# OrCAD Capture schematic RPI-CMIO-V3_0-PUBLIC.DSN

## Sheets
1 PAGE1 - CONTENTS: title: Raspberry Pi Compute Module IO Board; rev: 3.0; company: Raspberry Pi; note: RPI-CMIO
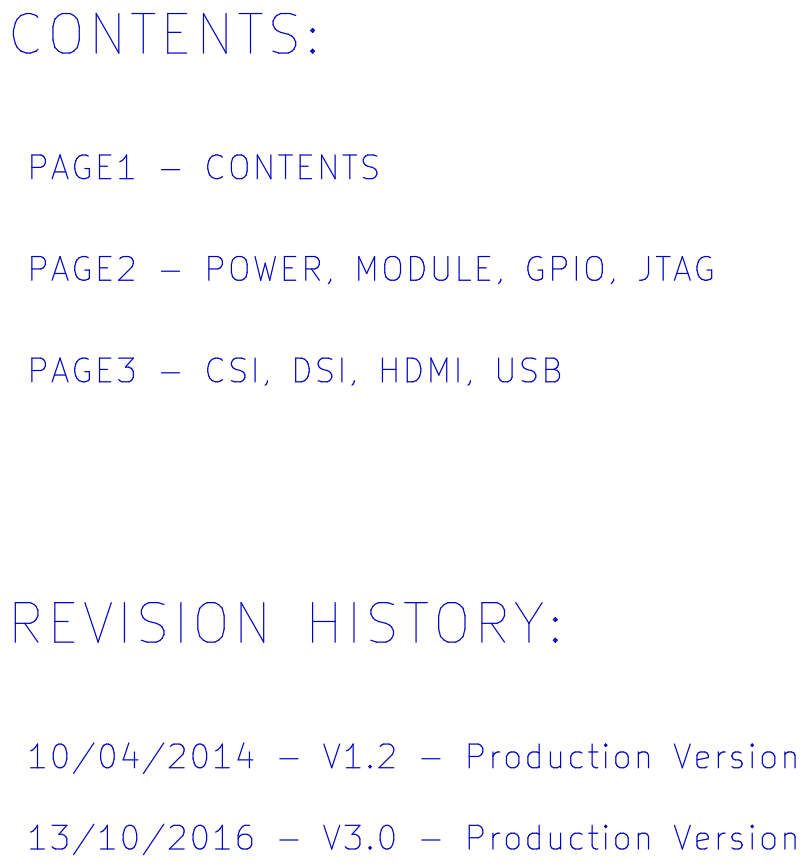
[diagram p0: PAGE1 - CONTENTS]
2 PAGE2 - PWR, CM, GPIO, JTAG: size A2
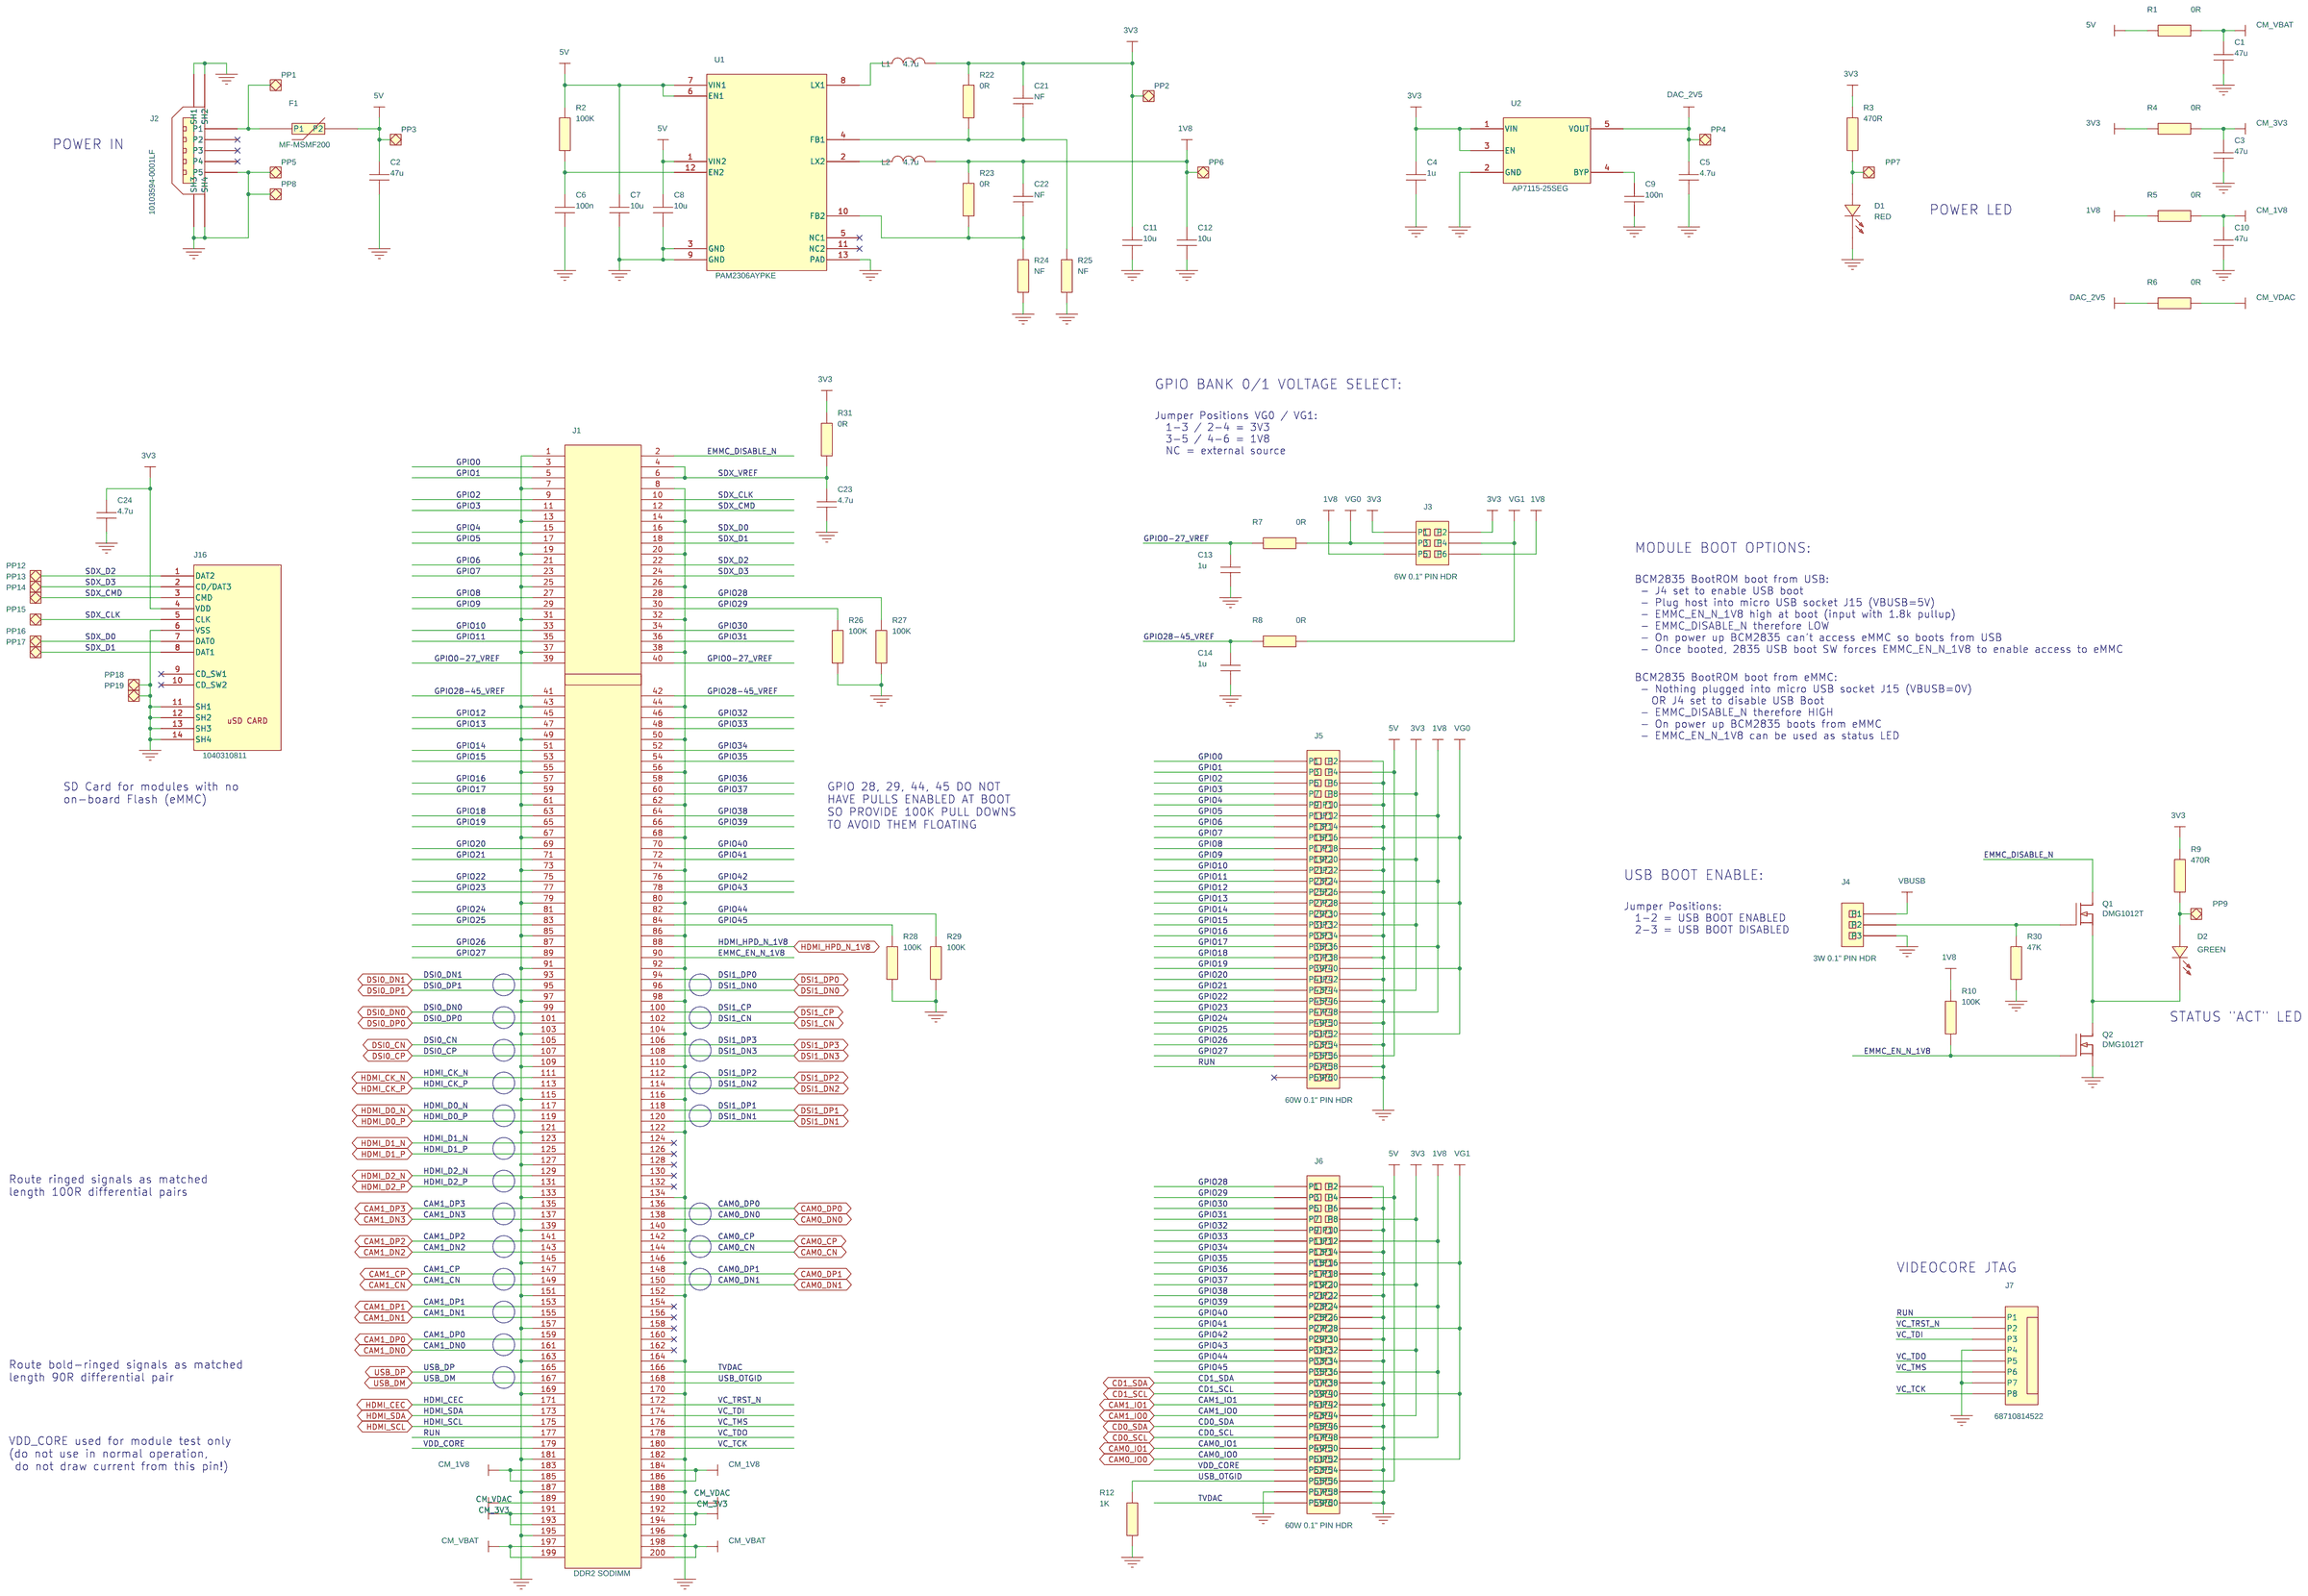
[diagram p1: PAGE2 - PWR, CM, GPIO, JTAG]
3 PAGE3 - CSI, DSI, HDMI, USB: size A2
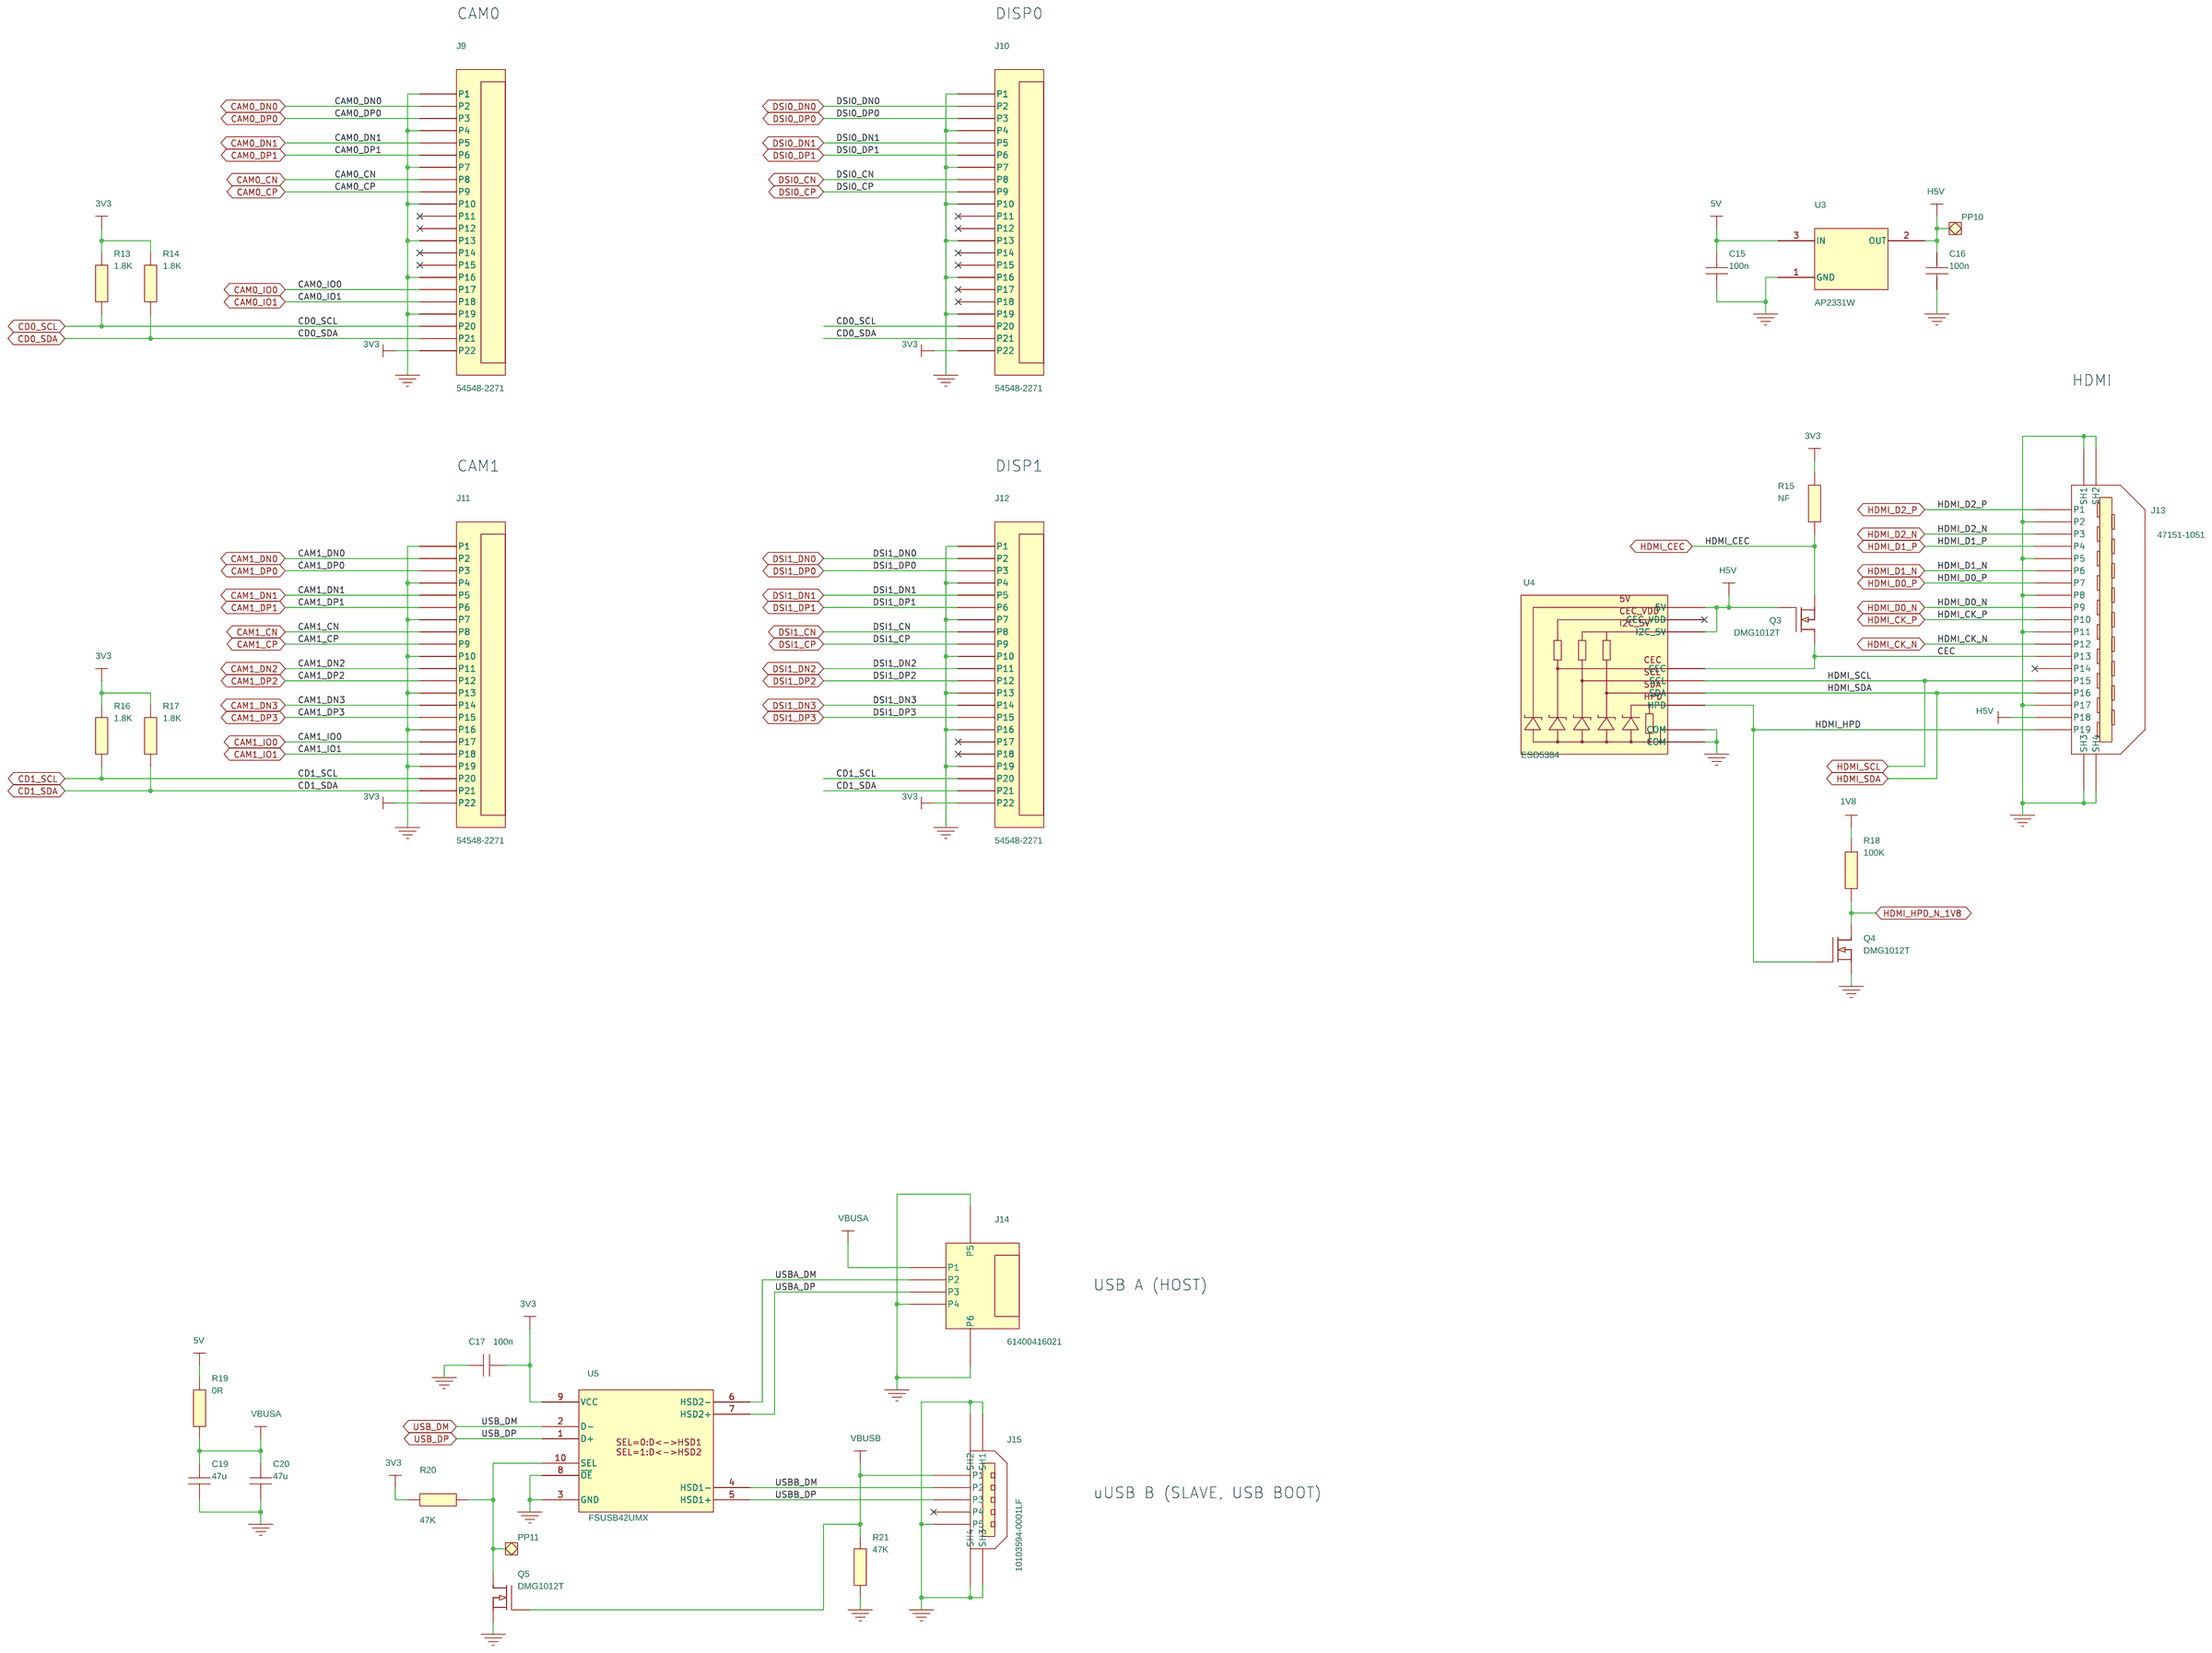
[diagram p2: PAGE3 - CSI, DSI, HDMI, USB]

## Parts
sheet PAGE2 - PWR, CM, GPIO, JTAG
C1  47u  [CAPC3216X180N]
C2  47u  [CAPC3216X180N]
C3  47u  [CAPC3216X180N]
C4  1u  [CAPC1005X55N]
C5  4.7u  [CAPC1608X90N]
C6  100n  [CAPC1005X55N]
C7  10u  [CAPC2012X145N]
C8  10u  [CAPC2012X145N]
C9  100n  [CAPC1005X55N]
C10  47u  [CAPC3216X180N]
C11  10u  [CAPC2012X145N]
C12  10u  [CAPC2012X145N]
C13  1u  [CAPC1005X55N]
C14  1u  [CAPC1005X55N]
C21  NF  [CAPC1005X55N]
C22  NF  [CAPC1005X55N]
C23  4.7u  [CAPC1608X90N]
C24  4.7u  [CAPC1608X90N]
D1  RED  [LEDC1608X80N]
D2  GREEN  [LEDC1608X80N]
F1  MF-MSMF200  [BOURNS_MF-MSMF150]
J1  DDR2 SODIMM  [FCI_10033853_CM]
J2  10103594-0001LF  [FCI_10103594-0001LF]
J3  6W 0.1" PIN HDR  [PINHDR_6W_2P54MM]
J4  3W 0.1" PIN HDR  [PINHDR_3W_2P54MM]
J5  60W 0.1" PIN HDR  [PINHDR_60W_2P54MM]
J6  60W 0.1" PIN HDR  [PINHDR_60W_2P54MM]
J7  68710814522  [WE_68710814522]
J16  1040310811  [MOLEX_1040310811]
L1  4.7u  [BOURNS_SRN4018]
L2  4.7u  [BOURNS_SRN4018]
PP1  PP_SMT_ROUND_2MM  [PP_SMT_R2MM]
PP2  PP_SMT_ROUND_2MM  [PP_SMT_R2MM]
PP3  PP_SMT_ROUND_2MM  [PP_SMT_R2MM]
PP4  PP_SMT_ROUND_2MM  [PP_SMT_R2MM]
PP5  PP_SMT_ROUND_2MM  [PP_SMT_R2MM]
PP6  PP_SMT_ROUND_2MM  [PP_SMT_R2MM]
PP7  PP_SMT_ROUND_2MM  [PP_SMT_R2MM]
PP8  PP_SMT_ROUND_2MM  [PP_SMT_R2MM]
PP9  PP_SMT_ROUND_2MM  [PP_SMT_R2MM]
PP12  PP_SMT_ROUND_2MM  [PP_SMT_R2MM]
PP13  PP_SMT_ROUND_2MM  [PP_SMT_R2MM]
PP14  PP_SMT_ROUND_2MM  [PP_SMT_R2MM]
PP15  PP_SMT_ROUND_2MM  [PP_SMT_R2MM]
PP16  PP_SMT_ROUND_2MM  [PP_SMT_R2MM]
PP17  PP_SMT_ROUND_2MM  [PP_SMT_R2MM]
PP18  PP_SMT_ROUND_2MM  [PP_SMT_R2MM]
PP19  PP_SMT_ROUND_2MM  [PP_SMT_R2MM]
Q1  DMG1012T  [SOT50P160X90-3N]
Q2  DMG1012T  [SOT50P160X90-3N]
R1  0R  [RESC2012X65N]
R2  100K  [RESC1005X40N]
R3  470R  [RESC1005X40N]
R4  0R  [RESC2012X65N]
R5  0R  [RESC2012X65N]
R6  0R  [RESC2012X65N]
R7  0R  [RESC2012X65N]
R8  0R  [RESC2012X65N]
R9  470R  [RESC1005X40N]
R10  100K  [RESC1005X40N]
R12  1K  [RESC1005X40N]
R22  0R  [RESC1005X40N]
R23  0R  [RESC1005X40N]
R24  NF  [RESC1005X40N]
R25  NF  [RESC1005X40N]
R26  100K  [RESC1005X40N]
R27  100K  [RESC1005X40N]
R28  100K  [RESC1005X40N]
R29  100K  [RESC1005X40N]
R30  47K  [RESC1005X40N]
R31  0R  [RESC2012X65N]
U1  PAM2306AYPKE  [DIODES_PAM2306]
U2  AP7115-25SEG  [SOT65P210X100-5N]
sheet PAGE3 - CSI, DSI, HDMI, USB
C15  100n  [CAPC1005X55N]
C16  100n  [CAPC1005X55N]
C17  100n  [CAPC1005X55N]
C19  47u  [CAPC3216X180N]
C20  47u  [CAPC3216X180N]
J9  54548-2271  [MOLEX_54548-2271]
J10  54548-2271  [MOLEX_54548-2271]
J11  54548-2271  [MOLEX_54548-2271]
J12  54548-2271  [MOLEX_54548-2271]
J13  47151-1051  [MOLEX_47151-1051]
J14  61400416021  [WURTH_61400416021]
J15  10103594-0001LF  [FCI_10103594-0001LF]
PP10  PP_SMT_ROUND_2MM  [PP_SMT_R2MM]
PP11  PP_SMT_ROUND_2MM  [PP_SMT_R2MM]
Q3  DMG1012T  [SOT50P160X90-3N]
Q4  DMG1012T  [SOT50P160X90-3N]
Q5  DMG1012T  [SOT50P160X90-3N]
R13  1.8K  [RESC1005X40N]
R14  1.8K  [RESC1005X40N]
R15  NF  [RESC1005X40N]
R16  1.8K  [RESC1005X40N]
R17  1.8K  [RESC1005X40N]
R18  100K  [RESC1005X40N]
R19  0R  [RESC2012X65N]
R20  47K  [RESC1005X40N]
R21  47K  [RESC1005X40N]
U3  AP2331W  [SOT95P280X135-3N]
U4  ESD5384  [ONSEMI_ESD5384]
U5  FSUSB42UMX  [FAIRCHILD_FSUSB42UMX]

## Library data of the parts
C1-C3 C10 C19 C20 = CAP_3216_6.3V_47u
C4 C13 C14 = CAP_1005_6.3V_1u
C5 C23 C24 = CAP_1608_6.3V_4.7u
C6 C9 C15-C17 = CAP_1005_6.3V_100n
C7 C8 C11 C12 = CAP_2012_6.3V_10u
C21 C22 = CAP_1005_NF
D1 = LED_1608_RED
D2 = LED_1608_GREEN
F1 = FUSE_POLY_2.0A_6V
J1 = CON_200W_DDR2SODIMM_CM
J2 J15 = CON_uUSB_B
J3 = CON_6W_PINHDR
J4 = CON_3W_PINHDR
J5 J6 = CON_60W_PINHDR
J7 = CON_FFC_8W
J16 = CON_uSD_1040310811
L1 L2 = IND_4u7_SRN4018-4R7M
PP1-PP19 = PP_SMT_ROUND_2MM
Q1-Q5 = MOSFET_N_DMG1012T
R1 R4-R8 R19 R31 = RES_2012_0R
R2 R10 R18 R26-R29 = RES_1005_100K
R3 R9 = RES_1005_470R
R12 = RES_1005_1K
R22 R23 = RES_1005_0R
R24 R25 = RES_1005_NF
R20 R21 R30 = RES_1005_47K
U1 = IC_SMPS_DUAL_1A_3V3_1V8
U2 = IC_AP7115-25SEG
J9-J12 = CON_22W_FFC_54548-2271
J13 = CON_HDMI_RA
J14 = CON_USBA_RA_PTH
R13 R14 R16 R17 = RES_1005_1.8K
R15 = RES_1005_27K
U3 = IC_AP2331W
U4 = IC_ESD5384
U5 = IC_MUX2-1_USB

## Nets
1V8: C12.1 C22.1 J3.5(P5) J3.6(P6) J5.12(P12) J5.24(P24) J5.36(P36) J5.48(P48) J6.12(P12) J6.24(P24) J6.36(P36) J6.48(P48) L2.2 PP6.1 R5.1 R10.1 R18.1 R23.1
3V3: C4.1 C11.1 C17.2 C21.1 C24.1 J3.1(P1) J3.2(P2) J5.8(P8) J5.20(P20) J5.32(P32) J5.44(P44) J6.8(P8) J6.20(P20) J6.32(P32) J6.44(P44) J9.22(P22) J10.22(P22) J11.22(P22) J12.22(P22) J16.4(VDD) L1.2 PP2.1 R3.1 R4.1 R9.1 R13.1 R14.1 R15.2 R16.1 R17.1 R20.1 R22.1 R31.2 U2.1(VIN) U2.3(EN) U5.9(VCC)
5V: C2.1 C7.1 C8.1 C15.1 F1.2(P2) J5.4(P4) J5.56(P56) J6.4(P4) J6.56(P56) PP3.1 R1.1 R2.1 R19.1 U1.1(VIN2) U1.6(EN1) U1.7(VIN1) U3.3(IN)
GND: C1.2 C2.2 C3.2 C4.2 C5.2 C6.2 C7.2 C8.2 C9.2 C10.2 C11.2 C12.2 C13.2 C14.2 C15.2 C16.2 C17.1 C19.2 C20.2 C23.2 C24.2 D1.1(CATHODE) J1.1 J1.7 J1.8 J1.13 J1.14 J1.19 J1.20 J1.25 J1.26 J1.31 J1.32 J1.37 J1.38 J1.43 J1.44 J1.49 J1.50 J1.55 J1.56 J1.61 J1.62 J1.67 J1.68 J1.73 J1.74 J1.79 J1.80 J1.85 J1.86 J1.91 J1.92 J1.97 J1.98 J1.103 J1.104 J1.109 J1.110 J1.115 J1.116 J1.121 J1.122 J1.127 J1.133 J1.134 J1.139 J1.140 J1.145 J1.146 J1.151 J1.152 J1.157 J1.163 J1.164 J1.169 J1.170 J1.181 J1.182 J1.187 J1.188 J1.195 J1.196 J2.5(P5) J2.6(SH1) J2.7(SH2) J2.8(SH3) J2.9(SH4) J4.3(P3) J5.2(P2) J5.6(P6) J5.10(P10) J5.14(P14) J5.18(P18) J5.22(P22) J5.26(P26) J5.30(P30) J5.34(P34) J5.38(P38) J5.42(P42) J5.46(P46) J5.50(P50) J5.54(P54) J5.58(P58) J5.60(P60) J6.2(P2) J6.6(P6) J6.10(P10) J6.14(P14) J6.18(P18) J6.22(P22) J6.26(P26) J6.30(P30) J6.34(P34) J6.38(P38) J6.42(P42) J6.46(P46) J6.50(P50) J6.54(P54) J6.57(P57) J6.58(P58) J6.60(P60) J7.4(P4) J7.7(P7) J9.1(P1) J9.4(P4) J9.7(P7) J9.10(P10) J9.13(P13) J9.16(P16) J9.19(P19) J10.1(P1) J10.4(P4) J10.7(P7) J10.10(P10) J10.13(P13) J10.16(P16) J10.19(P19) J11.1(P1) J11.4(P4) J11.7(P7) J11.10(P10) J11.13(P13) J11.16(P16) J11.19(P19) J12.1(P1) J12.4(P4) J12.7(P7) J12.10(P10) J12.13(P13) J12.16(P16) J12.19(P19) J13.2(P2) J13.5(P5) J13.8(P8) J13.11(P11) J13.17(P17) J13.20(SH1) J13.21(SH2) J13.22(SH3) J13.23(SH4) J14.4(P4) J14.5(P5) J14.6(P6) J15.5(P5) J15.6(SH1) J15.7(SH2) J15.8(SH3) J15.9(SH4) J16.6(VSS) J16.11(SH1) J16.12(SH2) J16.13(SH3) J16.14(SH4) PP5.1 PP8.1 PP18.1 PP19.1 Q2.2(S) Q4.2(S) Q5.2(S) R12.1 R21.2 R24.2 R25.2 R26.2 R27.2 R28.2 R29.2 R30.2 U1.3(GND) U1.9(GND) U1.13(PAD) U2.2(GND) U3.1(GND) U4.B2(COM) U4.C2(COM) U5.3(GND) U5.8(~{OE})
VBUSA: C19.1 C20.1 J14.1(P1) R19.2
VBUSB: J4.1(P1) J15.1(P1) Q5.1(G) R21.1
VDD_CORE: J1.179 J6.53(P53)
CAM0_CN: J1.144 J9.8(P8)
CAM0_CP: J1.142 J9.9(P9)
CAM0_DN0: J1.138 J9.2(P2)
CAM0_DN1: J1.150 J9.5(P5)
CAM0_DP0: J1.136 J9.3(P3)
CAM0_DP1: J1.148 J9.6(P6)
CAM0_IO0: J6.51(P51) J9.17(P17)
CAM0_IO1: J6.49(P49) J9.18(P18)
CAM1_CN: J1.149 J11.8(P8)
CAM1_CP: J1.147 J11.9(P9)
CAM1_DN0: J1.161 J11.2(P2)
CAM1_DN1: J1.155 J11.5(P5)
CAM1_DN2: J1.143 J11.11(P11)
CAM1_DN3: J1.137 J11.14(P14)
CAM1_DP0: J1.159 J11.3(P3)
CAM1_DP1: J1.153 J11.6(P6)
CAM1_DP2: J1.141 J11.12(P12)
CAM1_DP3: J1.135 J11.15(P15)
CAM1_IO0: J6.43(P43) J11.17(P17)
CAM1_IO1: J6.41(P41) J11.18(P18)
CD0_SCL: J6.47(P47) J9.20(P20) J10.20(P20) R13.2
CD0_SDA: J6.45(P45) J9.21(P21) J10.21(P21) R14.2
CD1_SCL: J6.39(P39) J11.20(P20) J12.20(P20) R16.2
CD1_SDA: J6.37(P37) J11.21(P21) J12.21(P21) R17.2
CEC: J13.13(P13) Q3.3(D) U4.A2(CEC)
CM_1V8: C10.1 J1.183 J1.184 J1.185 J1.186 R5.2
CM_3V3: C3.1 J1.191 J1.192 J1.193 J1.194 R4.2
CM_VBAT: C1.1 J1.197 J1.198 J1.199 J1.200 R1.2
CM_VDAC: J1.189 J1.190 R6.2
DAC_2V5: C5.1 PP4.1 R6.1 U2.5(VOUT)
DSI0_CN: J1.105 J10.8(P8)
DSI0_CP: J1.107 J10.9(P9)
DSI0_DN0: J1.99 J10.2(P2)
DSI0_DN1: J1.93 J10.5(P5)
DSI0_DP0: J1.101 J10.3(P3)
DSI0_DP1: J1.95 J10.6(P6)
DSI1_CN: J1.102 J12.8(P8)
DSI1_CP: J1.100 J12.9(P9)
DSI1_DN0: J1.96 J12.2(P2)
DSI1_DN1: J1.120 J12.5(P5)
DSI1_DN2: J1.114 J12.11(P11)
DSI1_DN3: J1.108 J12.14(P14)
DSI1_DP0: J1.94 J12.3(P3)
DSI1_DP1: J1.118 J12.6(P6)
DSI1_DP2: J1.112 J12.12(P12)
DSI1_DP3: J1.106 J12.15(P15)
EMMC_DISABLE_N: J1.2 Q1.3(D)
EMMC_EN_N_1V8: J1.90 Q2.1(G) R10.2
GPIO0: J1.3 J5.1(P1)
GPIO0-27_VREF: C13.1 J1.39 J1.40 R7.1
GPIO1: J1.5 J5.3(P3)
GPIO2: J1.9 J5.5(P5)
GPIO3: J1.11 J5.7(P7)
GPIO4: J1.15 J5.9(P9)
GPIO5: J1.17 J5.11(P11)
GPIO6: J1.21 J5.13(P13)
GPIO7: J1.23 J5.15(P15)
GPIO8: J1.27 J5.17(P17)
GPIO9: J1.29 J5.19(P19)
GPIO10: J1.33 J5.21(P21)
GPIO11: J1.35 J5.23(P23)
GPIO12: J1.45 J5.25(P25)
GPIO13: J1.47 J5.27(P27)
GPIO14: J1.51 J5.29(P29)
GPIO15: J1.53 J5.31(P31)
GPIO16: J1.57 J5.33(P33)
GPIO17: J1.59 J5.35(P35)
GPIO18: J1.63 J5.37(P37)
GPIO19: J1.65 J5.39(P39)
GPIO20: J1.69 J5.41(P41)
GPIO21: J1.71 J5.43(P43)
GPIO22: J1.75 J5.45(P45)
GPIO23: J1.77 J5.47(P47)
GPIO24: J1.81 J5.49(P49)
GPIO25: J1.83 J5.51(P51)
GPIO26: J1.87 J5.53(P53)
GPIO27: J1.89 J5.55(P55)
GPIO28: J1.28 J6.1(P1) R27.1
GPIO28-45_VREF: C14.1 J1.41 J1.42 R8.1
GPIO29: J1.30 J6.3(P3) R26.1
GPIO30: J1.34 J6.5(P5)
GPIO31: J1.36 J6.7(P7)
GPIO32: J1.46 J6.9(P9)
GPIO33: J1.48 J6.11(P11)
GPIO34: J1.52 J6.13(P13)
GPIO35: J1.54 J6.15(P15)
GPIO36: J1.58 J6.17(P17)
GPIO37: J1.60 J6.19(P19)
GPIO38: J1.64 J6.21(P21)
GPIO39: J1.66 J6.23(P23)
GPIO40: J1.70 J6.25(P25)
GPIO41: J1.72 J6.27(P27)
GPIO42: J1.76 J6.29(P29)
GPIO43: J1.78 J6.31(P31)
GPIO44: J1.82 J6.33(P33) R29.1
GPIO45: J1.84 J6.35(P35) R28.1
H5V: C16.1 J13.18(P18) PP10.1 Q3.1(G) U3.2(OUT) U4.A1(5V) U4.C1(I2C_5V)
HDMI_CEC: J1.171 Q3.2(S) R15.1
HDMI_CK_N: J1.111 J13.12(P12)
HDMI_CK_P: J1.113 J13.10(P10)
HDMI_D0_N: J1.117 J13.9(P9)
HDMI_D0_P: J1.119 J13.7(P7)
HDMI_D1_N: J1.123 J13.6(P6)
HDMI_D1_P: J1.125 J13.4(P4)
HDMI_D2_N: J1.129 J13.3(P3)
HDMI_D2_P: J1.131 J13.1(P1)
HDMI_HPD: J13.19(P19) Q4.1(G) U4.C3(HPD)
HDMI_HPD_N_1V8: J1.88 Q4.3(D) R18.2
HDMI_SCL: J1.175 J13.15(P15) U4.A3(SCL)
HDMI_SDA: J1.173 J13.16(P16) U4.B3(SDA)
RUN: J1.177 J5.57(P57) J7.1(P1)
SDX_CLK: J1.10 J16.5(CLK) PP15.1
SDX_CMD: J1.12 J16.3(CMD) PP14.1
SDX_D0: J1.16 J16.7(DAT0) PP16.1
SDX_D1: J1.18 J16.8(DAT1) PP17.1
SDX_D2: J1.22 J16.1(DAT2) PP12.1
SDX_D3: J1.24 J16.2(CD/DAT3) PP13.1
SDX_VREF: C23.1 J1.4 J1.6 R31.1
TVDAC: J1.166 J6.59(P59)
USB_DM: J1.167 U5.2(D-)
USB_DP: J1.165 U5.1(D+)
USB_OTGID: J1.168 J6.55(P55) R12.2
USBA_DM: J14.2(P2) U5.6(HSD2-)
USBA_DP: J14.3(P3) U5.7(HSD2+)
USBB_DM: J15.2(P2) U5.4(HSD1-)
USBB_DP: J15.3(P3) U5.5(HSD1+)
VC_TCK: J1.180 J7.8(P8)
VC_TDI: J1.174 J7.3(P3)
VC_TDO: J1.178 J7.5(P5)
VC_TMS: J1.176 J7.6(P6)
VC_TRST_N: J1.172 J7.2(P2)
VG0: J3.3(P3) J5.16(P16) J5.28(P28) J5.40(P40) J5.52(P52) R7.2
VG1: J3.4(P4) J6.16(P16) J6.28(P28) J6.40(P40) J6.52(P52) R8.2
N1195355: D2.2(ANODE) PP9.1 R9.2
N1195439: D2.1(CATHODE) Q1.2(S) Q2.3(D)
N1202496: C6.1 R2.2 U1.12(EN2)
N1202592: L1.1 U1.8(LX1)
N1202604: L2.1 U1.2(LX2)
N1202780: F1.1(P1) J2.1(P1) PP1.1
N1203166: C9.1 U2.4(BYP)
N1203318: D1.2(ANODE) PP7.1 R3.2
N1313759: C21.2 R22.2 R25.1 U1.4(FB1)
N1313939: C22.2 R23.2 R24.1 U1.10(FB2)
N1329395: PP11.1 Q5.3(D) R20.2 U5.10(SEL)
N1357591: J4.2(P2) Q1.1(G) R30.1

Not connected (* = marked no-connect by the designer): J1 124* 126* 128* 130* 132* 154* 156* 158* 160* 162*; J2 2(P2)* 3(P3)* 4(P4)*; J5 59(P59)*; J9 11(P11)* 12(P12)* 14(P14)* 15(P15)*; J10 11(P11)* 12(P12)* 14(P14)* 15(P15)* 17(P17)* 18(P18)*; J12 17(P17)* 18(P18)*; J13 14(P14)*; J15 4(P4)*; J16 9(CD_SW1)* 10(CD_SW2)*; U1 5(NC1)* 11(NC2)*; U4 B1(CEC_VDD)*

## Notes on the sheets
sheet 1
- CONTENTS:
- PAGE1 - CONTENTS
- PAGE2 - POWER, MODULE, GPIO, JTAG
- PAGE3 - CSI, DSI, HDMI, USB
- REVISION HISTORY:
- 10/04/2014 - V1.2 - Production Version
- 13/10/2016 - V3.0 - Production Version
sheet 2
- POWER IN
- POWER LED
- GPIO BANK 0/1 VOLTAGE SELECT:
- Jumper Positions VG0 / VG1:
    1-3 / 2-4 = 3V3
    3-5 / 4-6 = 1V8
    NC = external source
- MODULE BOOT OPTIONS:
- BCM2835 BootROM boot from USB:
   - J4 set to enable USB boot
   - Plug host into micro USB socket J15 (VBUSB=5V)
   - EMMC_EN_N_1V8 high at boot (input with 1.8k pullup)
   - EMMC_DISABLE_N therefore LOW
   - On power up BCM2835 can't access eMMC so boots from USB
   - Once booted, 2835 USB boot SW forces EMMC_EN_N_1V8 to enable access to eMMC
- BCM2835 BootROM boot from eMMC:
   - Nothing plugged into micro USB socket J15 (VBUSB=0V)
     OR J4 set to disable USB Boot
   - EMMC_DISABLE_N therefore HIGH
   - On power up BCM2835 boots from eMMC
   - EMMC_EN_N_1V8 can be used as status LED
- SD Card for modules with no
  on-board Flash (eMMC)
- GPIO 28, 29, 44, 45 DO NOT
  HAVE PULLS ENABLED AT BOOT
  SO PROVIDE 100K PULL DOWNS
  TO AVOID THEM FLOATING
- USB BOOT ENABLE:
- Jumper Positions:
    1-2 = USB BOOT ENABLED
    2-3 = USB BOOT DISABLED
- STATUS "ACT" LED
- Route ringed signals as matched
  length 100R differential pairs
- VIDEOCORE JTAG
- Route bold-ringed signals as matched
  length 90R differential pair
- VDD_CORE used for module test only
  (do not use in normal operation,
   do not draw current from this pin!)
sheet 3
- CAM0
- DISP0
- HDMI
- CAM1
- DISP1
- USB A (HOST)
- uUSB B (SLAVE, USB BOOT)
